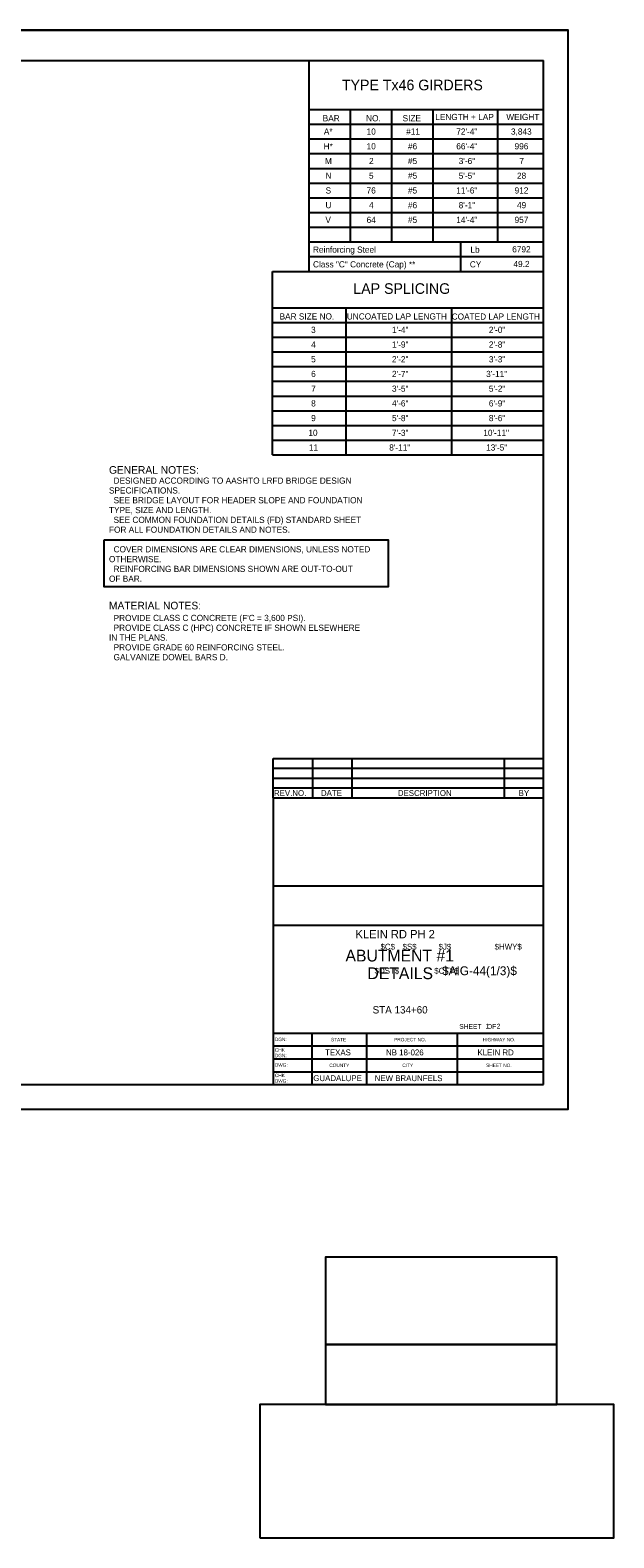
# Model space of a CAD drawing. Extents: x 970 to 1074, y 989 to 1045.
# Drawn here: x 1023.03 to 1034.93, y 989.07 to 1019.81 of the extents above; entities that cross this region are included whole.
import ezdxf

# ---------------------------------------------------------------- set-up
doc = ezdxf.new("R2010")
doc.units = 0
for name, color, linetype in [('BORD_lines_major', 7, 'Continuous'), ('BORD_lines_minor', 7, 'Continuous'), ('BORD_text_large_1', 7, 'Continuous'), ('BORD_text_large_2', 7, 'Continuous'), ('BORD_text_small_1', 7, 'Continuous'), ('BORD_text_small_3', 7, 'Continuous'), ('BORD_text_small_proj', 7, 'Continuous'), ('D_BATCH_PLOT', 7, 'Continuous'), ('D_SHEET', 7, 'Continuous'), ('D_SHEET_NUM_CODE', 7, 'Continuous'), ('D_SHEET_TXT_SUB_CODE', 7, 'Continuous'), ('Default', 7, 'Continuous'), ('Working Level 1', 7, 'Continuous')]:
    doc.layers.add(name, color=color, linetype=linetype)

msp = doc.modelspace()

# ---------------------------------------------------------------- linework, layer by layer
at = {"layer": 'BORD_lines_major'}
for p, q in [((1002.413, 1019.195), (1033.5, 1019.195)), ((1033.5, 998.313), (1033.5, 1019.195)), ((1002.413, 998.313), (1033.5, 998.313))]:
    msp.add_line(p, q, dxfattribs=at)
at = {"layer": 'BORD_lines_minor'}
for p, q in [((1027.988, 1004.963), (1033.5, 1004.963)), ((1027.988, 1004.163), (1027.988, 1004.963)), ((1028.788, 1004.963), (1028.788, 1004.163)), ((1029.588, 1004.963), (1029.588, 1004.163)), ((1032.7, 1004.163), (1032.7, 1004.963)), ((1027.988, 1004.763), (1033.5, 1004.763)), ((1027.988, 1004.563), (1033.5, 1004.563)), ((1027.988, 1004.363), (1033.5, 1004.363)), ((1027.988, 1004.163), (1033.5, 1004.163)), ((1027.988, 1004.163), (1027.988, 1002.363)), ((1027.988, 1002.363), (1033.5, 1002.363)), ((1027.988, 1002.363), (1027.988, 998.313)), ((1027.988, 1001.563), (1033.5, 1001.563)), ((1027.988, 999.363), (1033.5, 999.363)), ((1027.988, 999.1), (1033.5, 999.1)), ((1028.776, 999.363), (1028.776, 998.313)), ((1029.888, 999.363), (1029.888, 998.313)), ((1031.738, 999.363), (1031.738, 998.313)), ((1027.988, 998.838), (1033.5, 998.838)), ((1027.988, 998.575), (1033.5, 998.575))]:
    msp.add_line(p, q, dxfattribs=at)
at = {"layer": 'D_BATCH_PLOT'}
msp.add_lwpolyline([(1000, 997.813), (1034, 997.813), (1034, 1019.813), (1000, 1019.813)], close=True, dxfattribs=at)
at = {"layer": 'D_SHEET'}
for p, q in [((1000, 1019.813), (1034, 1019.813)), ((1034, 997.813), (1034, 1019.813)), ((1000, 997.813), (1034, 997.813))]:
    msp.add_line(p, q, dxfattribs=at)
at = {"layer": 'Default'}
for p in [(1029.876, 1019.195), (1033.5, 1011.955)]:
    msp.add_line(p, (1033.5, 1019.195), dxfattribs=at)
at = {"layer": 'Working Level 1'}
for p, q in [((1028.719, 1014.895), (1028.719, 1019.195)), ((1028.719, 1019.195), (1033.5, 1019.195)), ((1028.783, 1019.195), (1033.5, 1019.195)), ((1028.783, 1019.195), (1033.5, 1019.195)), ((1033.5, 1013.652), (1033.5, 1019.195)), ((1033.5, 1015.495), (1033.5, 1019.195)), ((1028.719, 1018.195), (1033.5, 1018.195)), ((1029.563, 1015.495), (1029.563, 1018.195)), ((1030.406, 1015.495), (1030.406, 1018.195)), ((1031.25, 1015.495), (1031.25, 1018.195)), ((1032.568, 1015.495), (1032.568, 1018.195)), ((1028.719, 1017.895), (1033.5, 1017.895)), ((1028.719, 1017.595), (1033.5, 1017.595)), ((1028.719, 1017.295), (1033.5, 1017.295)), ((1028.719, 1016.995), (1033.5, 1016.995)), ((1028.719, 1016.695), (1033.5, 1016.695)), ((1028.719, 1016.395), (1033.5, 1016.395)), ((1028.719, 1016.095), (1033.5, 1016.095)), ((1028.719, 1015.795), (1033.5, 1015.795)), ((1028.719, 1015.495), (1033.5, 1015.495)), ((1031.813, 1014.895), (1031.813, 1015.495)), ((1028.719, 1015.195), (1033.5, 1015.195)), ((1027.975, 1011.153), (1027.975, 1014.895)), ((1027.975, 1014.895), (1033.5, 1014.895)), ((1028.719, 1014.895), (1033.5, 1014.895)), ((1028.719, 1014.895), (1033.5, 1014.895)), ((1033.5, 1011.153), (1033.5, 1014.895)), ((1027.975, 1014.153), (1033.5, 1014.153)), ((1027.975, 1013.853), (1033.5, 1013.853)), ((1029.475, 1011.153), (1029.475, 1014.153)), ((1031.625, 1011.153), (1031.625, 1014.153)), ((1027.975, 1013.553), (1033.5, 1013.553)), ((1033.499, 1008.129), (1033.499, 1013.671)), ((1027.975, 1013.253), (1033.5, 1013.253)), ((1027.975, 1012.953), (1033.5, 1012.953)), ((1027.975, 1012.653), (1033.5, 1012.653)), ((1027.975, 1012.353), (1033.5, 1012.353)), ((1027.975, 1012.053), (1033.5, 1012.053)), ((1027.975, 1011.753), (1033.5, 1011.753)), ((1027.975, 1011.453), (1033.5, 1011.453)), ((1027.975, 1011.153), (1033.5, 1011.153))]:
    msp.add_line(p, q, dxfattribs=at)
for points in [[(1024.541, 1009.418), (1030.331, 1009.418), (1030.331, 1008.461), (1024.541, 1008.461)], [(1029.05, 993.014), (1033.768, 993.014), (1033.768, 994.795), (1029.05, 994.795)], [(1029.05, 991.788), (1033.768, 991.788), (1033.768, 993.014), (1029.05, 993.014)], [(1027.715, 989.071), (1034.931, 989.071), (1034.931, 991.788), (1027.715, 991.788)]]:
    msp.add_lwpolyline(points, close=True, dxfattribs=at)

# ---------------------------------------------------------------- texts
at = {"layer": 'BORD_lines_minor'}
for s, p in [('REV.NO.', (1028.002, 1004.198)), ('DATE', (1028.96, 1004.198)), ('DESCRIPTION', (1030.528, 1004.198)), ('BY', (1032.99, 1004.198))]:
    msp.add_text(s, height=0.12, rotation=359.9834, dxfattribs=at).set_placement(p)
msp.add_text('KLEIN RD PH 2', height=0.17, dxfattribs=at).set_placement((1029.665, 1001.296))
at = {"layer": 'BORD_text_large_1'}
for s, p in [('ABUTMENT #1', (1029.46, 1000.823)), ('DETAILS', (1029.907, 1000.463))]:
    msp.add_text(s, height=0.24, dxfattribs=at).set_placement(p)
at = {"layer": 'BORD_text_large_2'}
msp.add_text('STA 134+60', height=0.15, dxfattribs=at).set_placement((1030.014, 999.763))
at = {"layer": 'BORD_text_small_1'}
msp.add_text('SHEET   OF', height=0.0984, dxfattribs=at).set_placement((1031.78, 999.449))
at = {"layer": 'BORD_text_small_3'}
msp.add_text('1    2', height=0.0984, dxfattribs=at).set_placement((1032.316, 999.455))
at = {"layer": 'BORD_text_small_proj'}
for s, height, p in [('DGN:', 0.07, (1028.02, 999.199)), ('STATE', 0.07, (1029.164, 999.196)), ('PROJECT NO.', 0.07, (1030.452, 999.196)), ('HIGHWAY NO.', 0.07, (1032.258, 999.196)), ('CHK', 0.07, (1028.02, 998.984)), ('DGN:', 0.07, (1028.02, 998.871)), ('TEXAS', 0.12, (1029.044, 998.909)), ('KLEIN RD', 0.12, (1032.151, 998.909)), ('CHK', 0.07, (1028.02, 998.465)), ('DWG:', 0.07, (1028.02, 998.677)), ('GUADALUPE', 0.12, (1028.804, 998.384)), ('COUNTY', 0.07, (1029.13, 998.671)), ('NEW BRAUNFELS', 0.12, (1030.055, 998.384)), ('CITY', 0.07, (1030.619, 998.671)), ('SHEET NO.', 0.07, (1032.327, 998.671)), ('DWG:', 0.07, (1028.02, 998.352))]:
    msp.add_text(s, height=height, rotation=359.9834, dxfattribs=at).set_placement(p)
msp.add_text('NB 18-026', height=0.12, dxfattribs=at).set_placement((1030.287, 998.909))
at = {"layer": 'D_SHEET_NUM_CODE'}
msp.add_text('$AIG-44(1/3)$', height=0.18, dxfattribs=at).set_placement((1031.429, 1000.544))
at = {"layer": 'D_SHEET_TXT_SUB_CODE'}
for s, p in [('$C$', (1030.174, 1001.065)), ('$S$', (1030.624, 1001.065)), ('$J$', (1031.357, 1001.065)), ('$HWY$', (1032.501, 1001.065)), ('$DST$', (1030.055, 1000.574)), ('$CTY$', (1031.27, 1000.574))]:
    msp.add_text(s, height=0.12, dxfattribs=at).set_placement(p)
at = {"layer": 'Working Level 1'}
for s, height, p in [('TYPE Tx46 GIRDERS', 0.216, (1029.387, 1018.587)), ('BAR', 0.126, (1028.996, 1017.954)), ('NO.', 0.126, (1029.88, 1017.954)), ('SIZE', 0.126, (1030.625, 1017.954)), ('LENGTH + LAP', 0.126, (1031.29, 1017.98)), ('WEIGHT', 0.126, (1032.739, 1017.98)), ('A*', 0.126, (1029.019, 1017.682)), ('10', 0.126, (1029.891, 1017.682)), ('#11', 0.126, (1030.697, 1017.682)), ('72\'-4"', 0.126, (1031.719, 1017.682)), ('3,843', 0.126, (1032.834, 1017.682)), ('H*', 0.126, (1029.014, 1017.382)), ('10', 0.126, (1029.891, 1017.382)), ('#6', 0.126, (1030.734, 1017.382)), ('66\'-4"', 0.126, (1031.719, 1017.382)), ('996', 0.126, (1032.907, 1017.382)), ('M', 0.126, (1029.042, 1017.082)), ('2', 0.126, (1029.94, 1017.082)), ('#5', 0.126, (1030.734, 1017.082)), ('3\'-6"', 0.126, (1031.768, 1017.082)), ('7', 0.126, (1033.005, 1017.082)), ('N', 0.126, (1029.053, 1016.782)), ('5', 0.126, (1029.939, 1016.782)), ('#5', 0.126, (1030.734, 1016.782)), ('5\'-5"', 0.126, (1031.768, 1016.782)), ('28', 0.126, (1032.956, 1016.782)), ('S', 0.126, (1029.055, 1016.482)), ('76', 0.126, (1029.89, 1016.482)), ('#5', 0.126, (1030.734, 1016.482)), ('11\'-6"', 0.126, (1031.719, 1016.482)), ('912', 0.126, (1032.908, 1016.482)), ('V', 0.126, (1029.051, 1015.882)), ('U', 0.126, (1029.052, 1016.182)), ('64', 0.126, (1029.891, 1015.882)), ('4', 0.126, (1029.94, 1016.182)), ('#5', 0.126, (1030.734, 1015.882)), ('#6', 0.126, (1030.734, 1016.182)), ('14\'-4"', 0.126, (1031.719, 1015.882)), ('8\'-1"', 0.126, (1031.768, 1016.182)), ('957', 0.126, (1032.907, 1015.882)), ('49', 0.126, (1032.956, 1016.182)), ('Reinforcing Steel', 0.126, (1028.798, 1015.275)), ('Lb', 0.126, (1032.007, 1015.275)), ('6792', 0.126, (1032.859, 1015.282)), ('Class "C" Concrete (Cap) **', 0.126, (1028.798, 1014.975)), ('CY', 0.126, (1031.995, 1014.975)), ('49.2', 0.126, (1032.884, 1014.982)), ('LAP SPLICING', 0.216, (1029.62, 1014.436)), ('BAR SIZE NO.', 0.126, (1028.117, 1013.913)), ('UNCOATED LAP LENGTH', 0.126, (1029.487, 1013.913)), ('COATED LAP LENGTH', 0.126, (1031.625, 1013.91)), ('3', 0.126, (1028.759, 1013.64)), ('1\'-4"', 0.126, (1030.408, 1013.64)), ('2\'-0"', 0.126, (1032.383, 1013.64)), ('4', 0.126, (1028.762, 1013.34)), ('1\'-9"', 0.126, (1030.408, 1013.34)), ('2\'-8"', 0.126, (1032.383, 1013.34)), ('5', 0.126, (1028.76, 1013.04)), ('2\'-2"', 0.126, (1030.408, 1013.04)), ('3\'-3"', 0.126, (1032.383, 1013.04)), ('6', 0.126, (1028.76, 1012.74)), ('2\'-7"', 0.126, (1030.408, 1012.74)), ('3\'-11"', 0.126, (1032.327, 1012.74)), ('7', 0.126, (1028.762, 1012.44)), ('3\'-5"', 0.126, (1030.408, 1012.44)), ('5\'-2"', 0.126, (1032.383, 1012.44)), ('8', 0.126, (1028.76, 1012.14)), ('4\'-6"', 0.126, (1030.408, 1012.14)), ('6\'-9"', 0.126, (1032.383, 1012.14)), ('9', 0.126, (1028.76, 1011.84)), ('5\'-8"', 0.126, (1030.408, 1011.84)), ('8\'-6"', 0.126, (1032.383, 1011.84)), ('10', 0.126, (1028.704, 1011.54)), ('7\'-3"', 0.126, (1030.408, 1011.54)), ('10\'-11"', 0.126, (1032.27, 1011.54)), ('11', 0.126, (1028.714, 1011.24)), ('8\'-11"', 0.126, (1030.352, 1011.24)), ('13\'-5"', 0.126, (1032.327, 1011.24)), ('GENERAL NOTES:', 0.156, (1024.639, 1010.768)), ('SPECIFICATIONS.', 0.126, (1024.639, 1010.365)), ('  DESIGNED ACCORDING TO AASHTO LRFD BRIDGE DESIGN', 0.126, (1024.639, 1010.565)), ('  SEE BRIDGE LAYOUT FOR HEADER SLOPE AND FOUNDATION', 0.126, (1024.639, 1010.165)), ('TYPE, SIZE AND LENGTH. ', 0.126, (1024.639, 1009.965)), ('  SEE COMMON FOUNDATION DETAILS (FD) STANDARD SHEET', 0.126, (1024.639, 1009.765)), ('FOR ALL FOUNDATION DETAILS AND NOTES.', 0.126, (1024.639, 1009.565)), ('  COVER DIMENSIONS ARE CLEAR DIMENSIONS, UNLESS NOTED', 0.126, (1024.639, 1009.165)), ('OTHERWISE.', 0.126, (1024.639, 1008.965)), ('OF BAR.', 0.126, (1024.639, 1008.565)), ('  REINFORCING BAR DIMENSIONS SHOWN ARE OUT-TO-OUT', 0.126, (1024.639, 1008.765)), ('MATERIAL NOTES:', 0.156, (1024.639, 1008.002)), ("  PROVIDE CLASS C CONCRETE (F'C = 3,600 PSI).", 0.126, (1024.639, 1007.765)), ('IN THE PLANS.', 0.126, (1024.639, 1007.365)), ('  PROVIDE CLASS C (HPC) CONCRETE IF SHOWN ELSEWHERE', 0.126, (1024.639, 1007.565)), ('  GALVANIZE DOWEL BARS D.', 0.126, (1024.639, 1006.965)), ('  PROVIDE GRADE 60 REINFORCING STEEL.', 0.126, (1024.639, 1007.165))]:
    msp.add_text(s, height=height, dxfattribs=at).set_placement(p)

doc.saveas('drawing.dxf')
